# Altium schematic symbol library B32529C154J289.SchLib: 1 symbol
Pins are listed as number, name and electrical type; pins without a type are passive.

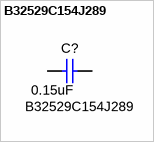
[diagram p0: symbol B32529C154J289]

## B32529C154J289
designator C?  value 0.15uF
CAP, FILM, 0.15uF, 63VDC, 5%, RADIAL-2P; Manufacturer: TDK; CompType: Film Capacitor; SymbolCreator: x0199378
pins: 1, 2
